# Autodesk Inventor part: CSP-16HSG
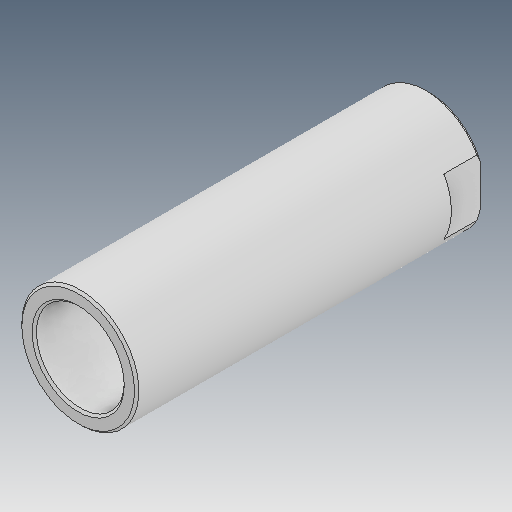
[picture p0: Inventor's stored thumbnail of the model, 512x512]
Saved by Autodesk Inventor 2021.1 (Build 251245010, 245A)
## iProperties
Created: 2021-06
Part Number: CSP-16HSG
Material: Ogólny
Document SubType Name: Modeling
Designer: user
Density: 1 g/cm^3
Appearance: Domyślna
Author: user
Revision Number: ÈÎºÎ
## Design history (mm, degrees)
feature "ÊäÈë1"
node "Bryła1"
